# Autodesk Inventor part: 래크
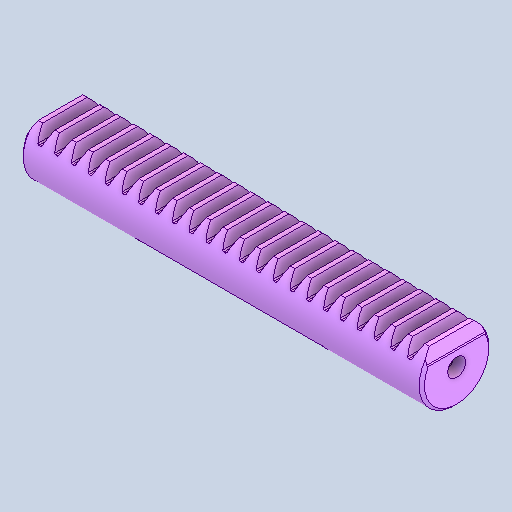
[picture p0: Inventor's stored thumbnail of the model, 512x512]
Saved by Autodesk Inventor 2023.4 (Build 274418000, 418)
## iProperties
Created: 2024-10
Part Number: 래크
Material: 강철, 탄소
Document SubType Name: Modeling
Designer: EDU
Density: 7.85 g/cm^3
Appearance: 기본값
Author: jhkim
Sending System: Autodesk Inventor 2025
Preprocessor: ST-DEVELOPER v20
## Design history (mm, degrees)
feature "솔리드1"
node "솔리드2"
